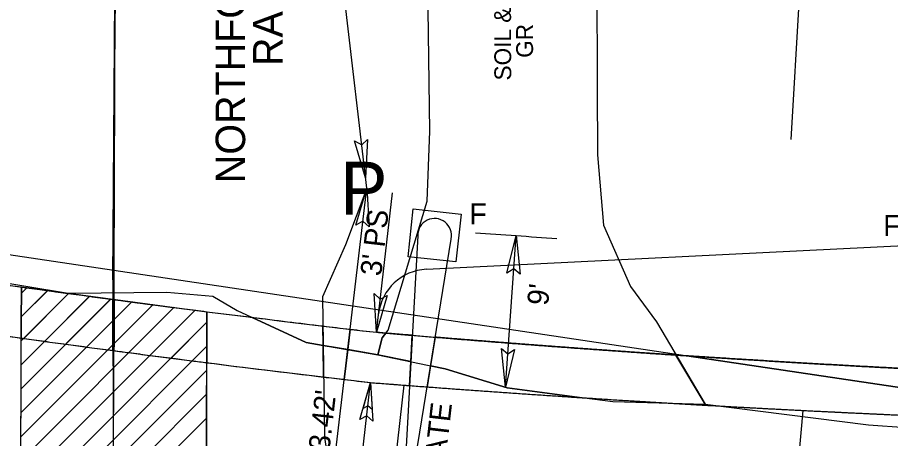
# Model space of a CAD drawing. Extents: x 1756964 to 1757438, y 736785 to 737067.
# Drawn here: x 1757129.6 to 1757181.4, y 736985.8 to 737010.8 of the extents above; entities that cross this region are included whole.
import ezdxf

# ---------------------------------------------------------------- set-up
doc = ezdxf.new("R2010")
doc.units = 0
for name, color, linetype in [('Exist Other Culture Fence Line', 7, 'Continuous'), ('Exist Railroads Standard Gauge', 7, 'Continuous'), ('Exist Roads EOP', 7, 'Continuous'), ('Exist Roads Soil', 7, 'Continuous'), ('Exist Roads Soil Text', 7, 'Continuous'), ('Exist Utilities Power Pole CELL', 7, 'Continuous'), ('Exist Utilities Power UG Cable SUE LOS B', 7, 'Continuous'), ('Exist Utilities Sanitary Sewer UG Line', 7, 'Continuous'), ('Gate 19 ft CELL', 7, 'Continuous'), ('Old_Level_18', 7, 'Continuous'), ('Old_Level_3', 7, 'Continuous'), ('Old_Level_7', 7, 'Continuous'), ('Prop Dimension', 7, 'Continuous'), ('Prop Horizontal Alignment Tick Label', 7, 'Continuous'), ('Prop Paved Shoulder', 7, 'Continuous'), ('Prop Shade Light', 7, 'Continuous'), ('Prop SS Fill Line', 7, 'Continuous'), ('Prop SS Fill Text', 7, 'Continuous'), ('Prop Superelevation Label', 7, 'Continuous'), ('Prop Terminator CELL', 7, 'Continuous'), ('Sheet Plan CELL', 7, 'Continuous')]:
    doc.layers.add(name, color=color, linetype=linetype)

msp = doc.modelspace()

# ---------------------------------------------------------------- linework, layer by layer
at = {"layer": 'Exist Other Culture Fence Line'}
msp.add_line((1757176.84, 737027.284), (1757175.445, 737003.531), dxfattribs=at)
at = {"layer": 'Exist Railroads Standard Gauge'}
for points in [[(1757135.242, 736995.205), (1757135.459, 737018.365), (1757136.418, 737046.14), (1757136.635, 737049.725)], [(1757135.242, 736995.205), (1757135.341, 736944.111), (1757135.323, 736924.976)]]:
    msp.add_lwpolyline(points, dxfattribs=at)
at = {"layer": 'Exist Roads EOP'}
msp.add_lwpolyline([(1757018.66, 737010.371), (1757061.104, 737003.358), (1757083.43, 737001.327), (1757098.831, 736998.502), (1757107.203, 736997.381), (1757114.704, 736996.445), (1757121.018, 736995.938), (1757127.563, 736995.243), (1757132.595, 736994.428), (1757138.449, 736994.482), (1757141.178, 736994.237), (1757142.611, 736993.402), (1757146.698, 736991.499), (1757150.958, 736990.769), (1757154.957, 736989.934), (1757158.624, 736988.801), (1757164.887, 736987.99), (1757170.366, 736987.834), (1757180.038, 736986.609), (1757200.139, 736985.19), (1757221.667, 736984.402), (1757240.419, 736984.021), (1757254.615, 736983.717), (1757256.718, 736983.7)], dxfattribs=at)
at = {"layer": 'Exist Roads Soil'}
for points in [[(1757150.958, 736990.769), (1757151.22, 736991.767), (1757151.563, 736992.222), (1757153.881, 736999.869), (1757154.037, 737004.022), (1757153.931, 737011.242), (1757152.809, 737017.847), (1757152.038, 737024.459), (1757151.659, 737030.744)], [(1757163.863, 737030.312), (1757163.911, 737018.105), (1757163.93, 737013.008), (1757163.955, 737006.581), (1757163.971, 737002.626), (1757164.342, 736998.444), (1757165.931, 736994.824), (1757167.468, 736992.712), (1757170.366, 736987.834)]]:
    msp.add_lwpolyline(points, dxfattribs=at)
at = {"layer": 'Exist Utilities Power UG Cable SUE LOS B'}
msp.add_lwpolyline([(1757150.298, 737000.642), (1757149.049, 736997.288), (1757147.67, 736994.203), (1757147.797, 736985.875), (1757149.578, 736974.231), (1757150.022, 736964.78), (1757150.11, 736948.278), (1757150.787, 736946.665)], dxfattribs=at)
at = {"layer": 'Exist Utilities Sanitary Sewer UG Line'}
msp.add_lwpolyline([(1757069.884, 737005.54), (1757256.718, 736977.66)], dxfattribs=at)
at = {"layer": 'Gate 19 ft CELL'}
for p, q in [((1757153.32, 736997.842), (1757152.279, 736978.958)), ((1757152.279, 736978.958), (1757155.296, 736997.631))]:
    msp.add_line(p, q, dxfattribs=at)
msp.add_lwpolyline([(1757155.582, 736996.277), (1757152.749, 736996.583), (1757153.055, 736999.417), (1757155.888, 736999.111)], close=True, dxfattribs=at)
msp.add_arc((1757154.32, 736997.847), 1, 347.5834, 180.2418, dxfattribs=at)
at = {"layer": 'Old_Level_18'}
msp.add_arc((1757223.496, 737921.422), 935.151, 265.524811, 272.035891, dxfattribs=at)
at = {"layer": 'Old_Level_7'}
for p, q in [((1757129.7, 736958.47), (1757129.827, 736994.787)), ((1757129.826, 736994.429), (1757130.142, 736994.745)), ((1757129.811, 736990.172), (1757133.886, 736994.247)), ((1757129.816, 736991.591), (1757132.638, 736994.413)), ((1757129.821, 736993.01), (1757131.39, 736994.579)), ((1757129.796, 736985.914), (1757137.63, 736993.748)), ((1757129.801, 736987.333), (1757136.382, 736993.915)), ((1757129.806, 736988.753), (1757135.134, 736994.081)), ((1757129.786, 736983.076), (1757140.126, 736993.416)), ((1757129.791, 736984.495), (1757138.878, 736993.582)), ((1757140.695, 736957.061), (1757140.822, 736993.324)), ((1757129.781, 736981.657), (1757140.82, 736992.695)), ((1757129.776, 736980.237), (1757140.815, 736991.276)), ((1757129.771, 736978.818), (1757140.81, 736989.857)), ((1757129.766, 736977.399), (1757140.805, 736988.438)), ((1757129.761, 736975.98), (1757140.8, 736987.019))]:
    msp.add_line(p, q, dxfattribs=at)
msp.add_lwpolyline([(1757129.827, 736994.787), (1757140.822, 736993.324), (1757140.695, 736957.061), (1757129.7, 736958.47)], close=True, dxfattribs=at)
msp.add_arc((1757258.672, 737920.867), 935, 262.079293, 262.758995, dxfattribs=at)
at = {"layer": 'Prop Dimension'}
for p, q in [((1757150.298, 737000.642), (1757148.414, 737016.82)), ((1757147.559, 736977.387), (1757150.298, 737000.642)), ((1757150.875, 736992.102), (1757151.835, 737000.377)), ((1757158.522, 736988.854), (1757159.154, 736997.832)), ((1757149.145, 736977.202), (1757150.529, 736989.122))]:
    msp.add_line(p, q, dxfattribs=at)
msp.add_arc((1757224.179, 737921.698), 926.151, 265.82424, 266.123668, dxfattribs=at)
at = {"layer": 'Prop Horizontal Alignment Tick Label'}
msp.add_line((1757135.082, 736924.976), (1757135.474, 737036.72), dxfattribs=at)
at = {"layer": 'Prop Paved Shoulder'}
msp.add_arc((1757258.672, 737920.867), 935, 261.751158, 263.379564, dxfattribs=at)
msp.add_spline([(1757150.875, 736992.102), (1757151.77, 736992.025), (1757152.665, 736991.95), (1757153.56, 736991.876), (1757154.455, 736991.802), (1757155.35, 736991.729), (1757156.245, 736991.657), (1757157.14, 736991.586), (1757158.035, 736991.516), (1757158.931, 736991.447), (1757159.826, 736991.378), (1757160.721, 736991.311), (1757161.617, 736991.244), (1757162.512, 736991.178), (1757163.408, 736991.113), (1757164.303, 736991.049), (1757165.199, 736990.986), (1757166.094, 736990.923), (1757166.99, 736990.862), (1757167.885, 736990.801), (1757168.781, 736990.741), (1757169.677, 736990.682), (1757170.572, 736990.624), (1757171.468, 736990.567), (1757172.364, 736990.51), (1757173.26, 736990.455), (1757174.156, 736990.4), (1757175.051, 736990.346), (1757175.947, 736990.293), (1757176.843, 736990.241), (1757177.739, 736990.19), (1757178.635, 736990.14), (1757179.531, 736990.09), (1757180.427, 736990.042), (1757181.323, 736989.994), (1757182.219, 736989.947), (1757183.115, 736989.901), (1757184.011, 736989.856), (1757184.907, 736989.811), (1757185.804, 736989.768), (1757186.7, 736989.725), (1757187.596, 736989.684), (1757188.492, 736989.643), (1757189.388, 736989.603), (1757190.284, 736989.564), (1757191.181, 736989.525), (1757192.077, 736989.488), (1757192.973, 736989.451), (1757193.869, 736989.416), (1757194.765, 736989.381), (1757195.662, 736989.347), (1757196.558, 736989.314), (1757197.454, 736989.282), (1757198.35, 736989.25), (1757199.247, 736989.22), (1757200.143, 736989.19), (1757201.039, 736989.161), (1757201.936, 736989.133), (1757202.832, 736989.106), (1757203.728, 736989.08), (1757204.624, 736989.055), (1757205.521, 736989.03), (1757206.417, 736989.007), (1757207.313, 736988.984), (1757208.209, 736988.962), (1757209.106, 736988.941), (1757210.002, 736988.921), (1757210.898, 736988.901), (1757211.794, 736988.883), (1757212.69, 736988.865), (1757213.587, 736988.849), (1757214.483, 736988.833), (1757215.379, 736988.818), (1757216.275, 736988.804), (1757217.171, 736988.79)], degree=3, dxfattribs=at)
at = {"layer": 'Prop Shade Light'}
for p, q in [((1757129.826, 736994.429), (1757129.827, 736994.787)), ((1757129.827, 736994.787), (1757129.826, 736994.429)), ((1757129.826, 736994.429), (1757130.14, 736994.744)), ((1757130.14, 736994.744), (1757129.826, 736994.429)), ((1757129.821, 736993.01), (1757131.382, 736994.572)), ((1757131.382, 736994.572), (1757129.821, 736993.01)), ((1757129.821, 736993.01), (1757129.826, 736994.429)), ((1757129.826, 736994.429), (1757129.821, 736993.01)), ((1757129.964, 736991.739), (1757132.627, 736994.402)), ((1757132.627, 736994.402), (1757129.964, 736991.739)), ((1757131.207, 736991.568), (1757133.872, 736994.233)), ((1757133.872, 736994.233), (1757131.207, 736991.568)), ((1757132.451, 736991.398), (1757135.119, 736994.066)), ((1757135.119, 736994.066), (1757132.451, 736991.398)), ((1757135.246, 736992.779), (1757135.244, 736994.049)), ((1757135.244, 736994.049), (1757135.246, 736992.779)), ((1757135.315, 736991.434), (1757137.618, 736993.736)), ((1757137.618, 736993.736), (1757135.315, 736991.434)), ((1757135.324, 736994.039), (1757135.32, 736992.853)), ((1757135.32, 736992.853), (1757135.324, 736994.039)), ((1757136.368, 736993.9), (1757135.32, 736992.853)), ((1757135.32, 736992.853), (1757136.368, 736993.9)), ((1757136.193, 736990.898), (1757138.87, 736993.574)), ((1757138.87, 736993.574), (1757136.193, 736990.898)), ((1757137.444, 736990.734), (1757140.123, 736993.413)), ((1757140.123, 736993.413), (1757137.444, 736990.734)), ((1757140.82, 736992.695), (1757140.822, 736993.324)), ((1757129.816, 736991.76), (1757129.821, 736993.01)), ((1757129.821, 736993.01), (1757129.816, 736991.76)), ((1757133.697, 736991.23), (1757135.246, 736992.779)), ((1757135.246, 736992.779), (1757133.697, 736991.23)), ((1757135.246, 736992.779), (1757135.32, 736992.853)), ((1757135.32, 736992.853), (1757135.246, 736992.779)), ((1757135.249, 736991.368), (1757135.246, 736992.779)), ((1757135.246, 736992.779), (1757135.249, 736991.368)), ((1757135.32, 736992.853), (1757135.315, 736991.434)), ((1757135.315, 736991.434), (1757135.32, 736992.853)), ((1757138.696, 736990.571), (1757140.82, 736992.695)), ((1757140.82, 736992.695), (1757138.696, 736990.571)), ((1757140.815, 736991.276), (1757140.82, 736992.695)), ((1757147.714, 736991.325), (1757147.696, 736992.476)), ((1757147.696, 736992.476), (1757147.714, 736991.325)), ((1757149.171, 736991.075), (1757149.314, 736992.284)), ((1757149.314, 736992.284), (1757149.171, 736991.075)), ((1757151.436, 736992.054), (1757150.875, 736992.102)), ((1757152.908, 736990.362), (1757152.994, 736991.923)), ((1757154.356, 736991.81), (1757154.082, 736990.117)), ((1757134.945, 736991.063), (1757135.249, 736991.368)), ((1757135.249, 736991.368), (1757134.945, 736991.063)), ((1757135.249, 736991.368), (1757135.315, 736991.434)), ((1757135.25, 736991.022), (1757135.249, 736991.368)), ((1757135.315, 736991.434), (1757135.314, 736991.014)), ((1757139.949, 736990.411), (1757140.815, 736991.276)), ((1757140.815, 736991.276), (1757139.949, 736990.411)), ((1757140.811, 736990.301), (1757140.815, 736991.276)), ((1757147.743, 736989.449), (1757147.714, 736991.325)), ((1757147.714, 736991.325), (1757149.171, 736991.075)), ((1757149.171, 736991.075), (1757147.714, 736991.325)), ((1757147.714, 736991.325), (1757147.743, 736989.449)), ((1757148.963, 736989.305), (1757149.171, 736991.075)), ((1757149.171, 736991.075), (1757148.963, 736989.305)), ((1757149.171, 736991.075), (1757150.958, 736990.769)), ((1757150.958, 736990.769), (1757149.171, 736991.075)), ((1757150.958, 736990.769), (1757152.908, 736990.362)), ((1757152.908, 736990.362), (1757150.958, 736990.769)), ((1757170.366, 736987.834), (1757168.633, 736990.751)), ((1757168.633, 736990.751), (1757170.366, 736987.834)), ((1757169.279, 736990.708), (1757196.378, 736986.664)), ((1757196.378, 736986.664), (1757169.279, 736990.708)), ((1757152.83, 736988.945), (1757152.908, 736990.362)), ((1757154.082, 736990.117), (1757153.88, 736988.866)), ((1757154.957, 736989.934), (1757154.082, 736990.117)), ((1757158.624, 736988.801), (1757154.957, 736989.934)), ((1757163.071, 736988.225), (1757158.624, 736988.801)), ((1757168.578, 736987.885), (1757170.366, 736987.834)), ((1757170.366, 736987.834), (1757171.114, 736987.739))]:
    msp.add_line(p, q, dxfattribs=at)
for points in [[(1757140.822, 736993.324), (1757140.82, 736992.695), (1757140.815, 736991.276), (1757140.811, 736990.301)], [(1757147.714, 736991.325), (1757146.698, 736991.499), (1757143.503, 736992.987)], [(1757143.503, 736992.987), (1757146.698, 736991.499), (1757147.714, 736991.325)], [(1757151.436, 736992.054), (1757151.22, 736991.767), (1757150.958, 736990.769)], [(1757150.958, 736990.769), (1757151.22, 736991.767), (1757151.436, 736992.054)], [(1757159.066, 736991.072), (1757158.522, 736988.854), (1757158.282, 736991.139), (1757158.66, 736990.825), (1757159.066, 736991.072)], [(1757154.082, 736990.117), (1757154.957, 736989.934), (1757158.624, 736988.801), (1757163.071, 736988.225)]]:
    msp.add_lwpolyline(points, dxfattribs=at)
for centre, radius, start, end in [((1757258.672, 737920.867), 935, 261.751158, 262.079293), ((1757258.672, 737920.867), 935, 262.079293, 262.098655), ((1757258.672, 737920.867), 935, 262.098655, 262.175523), ((1757258.672, 737920.867), 935, 262.175523, 262.25247), ((1757258.672, 737920.867), 935, 262.25247, 262.329495), ((1757258.672, 737920.867), 935, 262.329495, 262.406599), ((1757258.672, 737920.867), 935, 262.406599, 262.414306), ((1757258.672, 737920.867), 935, 262.414306, 262.419274), ((1757258.672, 737920.867), 935, 262.419274, 262.483783), ((1757258.672, 737920.867), 935, 262.483783, 262.561047), ((1757258.672, 737920.867), 935, 262.561047, 262.638391), ((1757258.672, 737920.867), 935, 262.638391, 262.715815), ((1757258.672, 737920.867), 935, 262.715815, 262.758995), ((1757258.672, 737920.867), 935, 262.758995, 262.924559), ((1757258.672, 737920.867), 935, 262.924559, 263.183448), ((1757258.672, 737920.867), 938, 261.751158, 263.379564), ((1757258.672, 737920.867), 938, 261.751158, 262.104133), ((1757258.672, 737920.867), 935, 263.183448, 263.283261), ((1757258.672, 737920.867), 935, 263.283261, 263.379564), ((1757258.672, 737920.867), 938, 262.104133, 262.11324), ((1757258.672, 737920.867), 938, 262.11324, 262.189877), ((1757258.672, 737920.867), 938, 262.189877, 262.266592), ((1757258.672, 737920.867), 938, 262.266592, 262.343386), ((1757258.672, 737920.867), 938, 262.343386, 262.420258), ((1757258.672, 737920.867), 938, 262.420258, 262.439073), ((1757258.672, 737920.867), 938, 262.443008, 262.497208), ((1757258.672, 737920.867), 938, 262.497208, 262.574239), ((1757258.672, 737920.867), 938, 262.574239, 262.651349), ((1757258.672, 737920.867), 938, 262.651349, 262.728539), ((1757258.672, 737920.867), 938, 262.728539, 262.781625), ((1757258.672, 737920.867), 938, 262.781625, 263.208194), ((1757258.672, 737920.867), 938, 263.208194, 263.283261), ((1757258.672, 737920.867), 938, 263.283261, 263.379564), ((1757223.496, 737921.422), 935.151, 265.5905, 265.601637)]:
    msp.add_arc(centre, radius, start, end, dxfattribs=at)
for points in [[(1757152.994, 736991.923), (1757152.665, 736991.95), (1757151.77, 736992.025), (1757151.436, 736992.054)], [(1757169.279, 736990.708), (1757168.781, 736990.741), (1757168.633, 736990.751)], [(1757172.945, 736990.474), (1757172.364, 736990.51), (1757171.468, 736990.567), (1757170.572, 736990.624), (1757169.677, 736990.682), (1757169.279, 736990.708)], [(1757195.048, 736989.37), (1757194.765, 736989.381), (1757193.869, 736989.416), (1757192.973, 736989.451), (1757192.077, 736989.488), (1757191.181, 736989.525), (1757190.284, 736989.564), (1757189.388, 736989.603), (1757188.492, 736989.643), (1757187.596, 736989.684), (1757186.7, 736989.725), (1757185.804, 736989.768), (1757184.907, 736989.811), (1757184.011, 736989.856), (1757183.115, 736989.901), (1757182.219, 736989.947), (1757181.323, 736989.994), (1757180.427, 736990.042), (1757179.531, 736990.09), (1757178.635, 736990.14), (1757177.739, 736990.19), (1757176.843, 736990.241), (1757175.947, 736990.293), (1757175.051, 736990.346), (1757174.156, 736990.4), (1757173.26, 736990.455), (1757172.945, 736990.474)], [(1757150.529, 736989.122), (1757151.427, 736989.052), (1757152.326, 736988.983), (1757153.225, 736988.915), (1757154.123, 736988.848), (1757155.022, 736988.781), (1757155.921, 736988.716), (1757156.819, 736988.651), (1757157.718, 736988.587), (1757158.617, 736988.524), (1757159.516, 736988.462), (1757160.415, 736988.401), (1757161.314, 736988.341), (1757162.212, 736988.281), (1757163.111, 736988.223), (1757164.01, 736988.165), (1757164.909, 736988.108), (1757165.808, 736988.052), (1757166.707, 736987.997), (1757167.606, 736987.943), (1757168.505, 736987.889), (1757169.405, 736987.837), (1757170.304, 736987.785), (1757171.203, 736987.735), (1757172.102, 736987.685), (1757173.001, 736987.636), (1757173.9, 736987.587), (1757174.799, 736987.54), (1757175.698, 736987.494), (1757176.598, 736987.448), (1757177.497, 736987.403), (1757178.396, 736987.359), (1757179.295, 736987.316), (1757180.195, 736987.274), (1757181.094, 736987.233), (1757181.993, 736987.193), (1757182.892, 736987.153), (1757183.792, 736987.115), (1757184.691, 736987.077), (1757185.59, 736987.04), (1757186.489, 736987.004), (1757187.389, 736986.969), (1757188.288, 736986.934), (1757189.187, 736986.901), (1757190.086, 736986.868), (1757190.986, 736986.836), (1757191.885, 736986.806), (1757192.784, 736986.776), (1757193.684, 736986.746), (1757194.583, 736986.718), (1757195.482, 736986.691), (1757196.381, 736986.664), (1757197.281, 736986.639), (1757198.18, 736986.614), (1757199.079, 736986.59), (1757199.978, 736986.567), (1757200.877, 736986.545), (1757201.777, 736986.523), (1757202.676, 736986.503), (1757203.575, 736986.483), (1757204.474, 736986.464), (1757205.373, 736986.447), (1757206.272, 736986.429), (1757207.171, 736986.413), (1757208.071, 736986.398), (1757208.97, 736986.384), (1757209.869, 736986.37), (1757210.768, 736986.357), (1757211.667, 736986.346), (1757212.566, 736986.335), (1757213.465, 736986.325), (1757214.364, 736986.315), (1757215.262, 736986.307), (1757216.161, 736986.299), (1757217.06, 736986.293)], [(1757150.529, 736989.122), (1757151.427, 736989.052), (1757151.598, 736989.039)], [(1757153.88, 736988.866), (1757154.123, 736988.848), (1757155.022, 736988.781), (1757155.921, 736988.716), (1757156.819, 736988.651), (1757157.718, 736988.587), (1757158.617, 736988.524), (1757159.516, 736988.462), (1757160.415, 736988.401), (1757161.314, 736988.341), (1757162.212, 736988.281), (1757163.071, 736988.225)], [(1757163.071, 736988.225), (1757163.111, 736988.223), (1757164.01, 736988.165), (1757164.909, 736988.108), (1757165.808, 736988.052), (1757166.707, 736987.997), (1757167.606, 736987.943), (1757168.505, 736987.889), (1757168.578, 736987.885)], [(1757171.114, 736987.739), (1757171.203, 736987.735), (1757172.102, 736987.685), (1757172.682, 736987.653)]]:
    msp.add_spline(points, degree=3, dxfattribs=at)
for points in [[(1757168.633, 736990.751), (1757168.384, 736990.767), (1757168.135, 736990.784), (1757167.885, 736990.801), (1757167.587, 736990.821), (1757167.288, 736990.841), (1757166.99, 736990.862), (1757166.691, 736990.882), (1757166.393, 736990.902), (1757166.094, 736990.923), (1757165.796, 736990.944), (1757165.497, 736990.965), (1757165.199, 736990.986), (1757164.9, 736991.007), (1757164.602, 736991.028), (1757164.303, 736991.049), (1757164.005, 736991.07), (1757163.706, 736991.091), (1757163.408, 736991.113), (1757163.109, 736991.135), (1757162.811, 736991.156), (1757162.512, 736991.178), (1757162.214, 736991.2), (1757161.915, 736991.222), (1757161.617, 736991.244), (1757161.318, 736991.266), (1757161.02, 736991.288), (1757160.721, 736991.311), (1757160.423, 736991.333), (1757160.124, 736991.356), (1757159.826, 736991.378), (1757159.527, 736991.401), (1757159.229, 736991.424), (1757158.931, 736991.447), (1757158.632, 736991.47), (1757158.334, 736991.493), (1757158.035, 736991.516), (1757157.737, 736991.539), (1757157.439, 736991.563), (1757157.14, 736991.586), (1757156.842, 736991.61), (1757156.543, 736991.633), (1757156.245, 736991.657), (1757155.947, 736991.681), (1757155.648, 736991.705), (1757155.35, 736991.729), (1757155.051, 736991.753), (1757154.753, 736991.778), (1757154.455, 736991.802), (1757154.422, 736991.805), (1757154.389, 736991.807), (1757154.356, 736991.81)], [(1757151.779, 736989.025), (1757151.961, 736989.011), (1757152.144, 736988.997), (1757152.326, 736988.983), (1757152.494, 736988.97), (1757152.662, 736988.957), (1757152.83, 736988.945)], [(1757172.682, 736987.653), (1757172.788, 736987.647), (1757172.895, 736987.641), (1757173.001, 736987.636), (1757173.301, 736987.619), (1757173.6, 736987.603), (1757173.9, 736987.587), (1757174.2, 736987.571), (1757174.5, 736987.556), (1757174.799, 736987.54), (1757175.099, 736987.524), (1757175.399, 736987.509), (1757175.698, 736987.494), (1757175.998, 736987.478), (1757176.298, 736987.463), (1757176.598, 736987.448), (1757176.897, 736987.433), (1757177.197, 736987.418), (1757177.497, 736987.403), (1757177.797, 736987.389), (1757178.096, 736987.374), (1757178.396, 736987.359), (1757178.696, 736987.345), (1757178.996, 736987.331), (1757179.295, 736987.316), (1757179.595, 736987.302), (1757179.895, 736987.288), (1757180.195, 736987.274), (1757180.494, 736987.26), (1757180.794, 736987.247), (1757181.094, 736987.233), (1757181.394, 736987.219), (1757181.693, 736987.206), (1757181.993, 736987.193), (1757182.293, 736987.179), (1757182.593, 736987.166), (1757182.892, 736987.153), (1757183.192, 736987.14), (1757183.492, 736987.127), (1757183.792, 736987.115), (1757184.091, 736987.102), (1757184.391, 736987.089), (1757184.691, 736987.077), (1757184.991, 736987.064), (1757185.29, 736987.052), (1757185.59, 736987.04), (1757185.89, 736987.028), (1757186.19, 736987.016), (1757186.489, 736987.004), (1757186.789, 736986.992), (1757187.089, 736986.98), (1757187.389, 736986.969), (1757187.688, 736986.957), (1757187.988, 736986.946), (1757188.288, 736986.934), (1757188.588, 736986.923), (1757188.887, 736986.912), (1757189.187, 736986.901), (1757189.487, 736986.89), (1757189.787, 736986.879), (1757190.086, 736986.868), (1757190.386, 736986.857), (1757190.686, 736986.847), (1757190.986, 736986.836), (1757191.285, 736986.826), (1757191.585, 736986.816), (1757191.885, 736986.806), (1757192.185, 736986.795), (1757192.485, 736986.785), (1757192.784, 736986.776), (1757193.084, 736986.766), (1757193.384, 736986.756), (1757193.684, 736986.746), (1757193.983, 736986.737), (1757194.283, 736986.727), (1757194.583, 736986.718), (1757194.676, 736986.715), (1757194.769, 736986.712), (1757194.863, 736986.71)]]:
    msp.add_open_spline(points, degree=3, dxfattribs=at)
at = {"layer": 'Prop SS Fill Line'}
for p, q in [((1757153.832, 736995.839), (1757185.841, 736997.424)), ((1757150.875, 736992.102), (1757150.96, 736992.833))]:
    msp.add_line(p, q, dxfattribs=at)
msp.add_arc((1757153.981, 736992.842), 3, 92.8361, 173.3796, dxfattribs=at)
at = {"layer": 'Prop Superelevation Label'}
for p, q in [((1757152.499, 736988.97), (1757149.096, 736959.104)), ((1757176.151, 736987.471), (1757175.01, 736974.558))]:
    msp.add_line(p, q, dxfattribs=at)
at = {"layer": 'Prop Terminator CELL'}
for points in [[(1757150.352, 737003.533), (1757150.228, 737001.253), (1757149.569, 737003.454), (1757149.999, 737003.215)], [(1757149.654, 736998.452), (1757150.298, 737000.642), (1757150.435, 736998.349), (1757150.07, 736998.681)], [(1757158.609, 736995.615), (1757159.154, 736997.832), (1757159.394, 736995.547), (1757159.015, 736995.862)], [(1757151.519, 736994.292), (1757150.875, 736992.102), (1757150.738, 736994.395), (1757151.102, 736994.064)], [(1757159.066, 736991.072), (1757158.522, 736988.854), (1757158.282, 736991.139), (1757158.66, 736990.825)], [(1757149.885, 736986.931), (1757150.529, 736989.122), (1757150.665, 736986.828), (1757150.301, 736987.16)], [(1757150.078, 736987.588), (1757150.529, 736989.122), (1757150.624, 736987.516), (1757150.37, 736987.748)]]:
    msp.add_lwpolyline(points, close=True, dxfattribs=at)
at = {"layer": 'Sheet Plan CELL'}
msp.add_line((1757135.242, 736995.205), (1757135.64, 737049.725), dxfattribs=at)

# ---------------------------------------------------------------- texts
at = {"layer": 'Exist Roads Soil Text'}
for s, p in [('SOIL &', (1757158.867, 737007.029)), ('GR', (1757160.161, 737008.373))]:
    msp.add_text(s, height=1, rotation=90.2226, dxfattribs=at).set_placement(p)
at = {"layer": 'Exist Utilities Power Pole CELL'}
msp.add_text('P', height=3.128, rotation=360, dxfattribs=at).set_placement((1757148.734, 736999.079))
at = {"layer": 'Old_Level_3'}
for s, p in [('RAILWAY COMPANY', (1757145.309, 737007.882)), ('NORTHFOLK SOUTHERN', (1757143.09, 737000.939))]:
    msp.add_text(s, height=1.75, rotation=90, dxfattribs=at).set_placement(p)
at = {"layer": 'Prop Dimension'}
for s, p in [("3' PS", (1757151.15, 736995.396)), ("9'", (1757161.036, 736993.649)), ("23.42'", (1757147.977, 736984.121)), ("19' GATE", (1757154.529, 736980.716))]:
    msp.add_text(s, height=1.25, rotation=83.3796, dxfattribs=at).set_placement(p)
at = {"layer": 'Prop SS Fill Text'}
for p in [(1757156.387, 736998.497), (1757180.917, 736997.802)]:
    msp.add_text('F', height=1.25, rotation=360, dxfattribs=at).set_placement(p)

doc.saveas('drawing.dxf')
